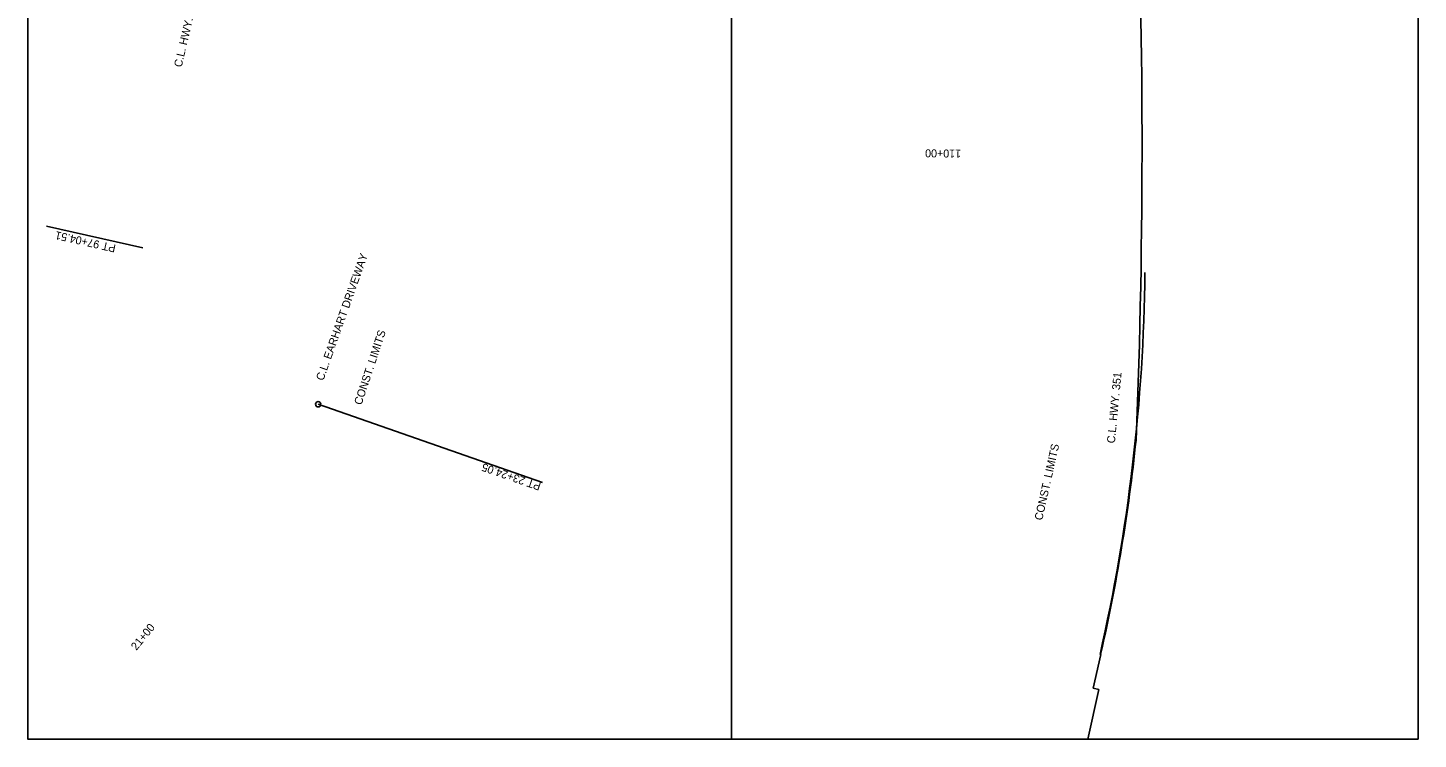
# Model space of a CAD drawing. Extents: x 1712161 to 1713203, y 549259 to 550855.
# Drawn here: x 1712161 to 1713203, y 549259 to 549792 of the extents above; entities that cross this region are included whole.
import ezdxf

# ---------------------------------------------------------------- set-up
doc = ezdxf.new("R2010")
doc.units = 0
for name, color, linetype in [('R_Contour Annot', 7, 'Continuous'), ('R_Contours', 7, 'Continuous'), ('R_Erosion', 7, 'Continuous'), ('R_Horz Alg Annot', 7, 'Continuous'), ('R_MOT', 7, 'Continuous')]:
    doc.layers.add(name, color=color, linetype=linetype)

msp = doc.modelspace()

# ---------------------------------------------------------------- linework, layer by layer
at = {"layer": 'R_Contour Annot'}
msp.add_lwpolyline([(1712361.5, 550854.5), (1712688.2, 550854.5), (1712688.2, 549259.2), (1712160.6, 549259.2), (1712160.6, 550443.2), (1712210, 550443.2), (1712210, 550620.8), (1712227.8, 550620.8), (1712227.8, 550639), (1712224.6, 550639), (1712224.6, 550716.7)], dxfattribs=at)
msp.add_lwpolyline([(1712361.5, 550854.5), (1712688.2, 550854.5), (1712688.2, 549259.2), (1712160.6, 549259.2), (1712160.6, 550443.2), (1712210, 550443.2), (1712210, 550620.8), (1712227.8, 550620.8), (1712227.8, 550639), (1712224.6, 550639), (1712224.6, 550716.7)], dxfattribs=at)
msp.add_lwpolyline([(1712361.5, 550854.5), (1712688.2, 550854.5), (1712688.2, 549259.2), (1712160.6, 549259.2), (1712160.6, 550443.2), (1712210, 550443.2), (1712210, 550620.8), (1712227.8, 550620.8), (1712227.8, 550639), (1712224.6, 550639), (1712224.6, 550716.7)], dxfattribs=at)
msp.add_lwpolyline([(1712361.5, 550854.5), (1712688.2, 550854.5), (1712688.2, 549259.2), (1712160.6, 549259.2), (1712160.6, 550443.2), (1712210, 550443.2), (1712210, 550620.8), (1712227.8, 550620.8), (1712227.8, 550639), (1712224.6, 550639), (1712224.6, 550716.7)], dxfattribs=at)
msp.add_lwpolyline([(1712361.5, 550854.5), (1712688.2, 550854.5), (1712688.2, 549259.2), (1712160.6, 549259.2), (1712160.6, 550443.2), (1712210, 550443.2), (1712210, 550620.8), (1712227.8, 550620.8), (1712227.8, 550639), (1712224.6, 550639), (1712224.6, 550716.7)], dxfattribs=at)
msp.add_lwpolyline([(1712361.5, 550854.5), (1712688.2, 550854.5), (1712688.2, 549259.2), (1712160.6, 549259.2), (1712160.6, 550443.2), (1712210, 550443.2), (1712210, 550620.8), (1712227.8, 550620.8), (1712227.8, 550639), (1712224.6, 550639), (1712224.6, 550716.7)], dxfattribs=at)
msp.add_lwpolyline([(1712361.5, 550854.5), (1712688.2, 550854.5), (1712688.2, 549259.2), (1712160.6, 549259.2), (1712160.6, 550443.2), (1712210, 550443.2), (1712210, 550620.8), (1712227.8, 550620.8), (1712227.8, 550639), (1712224.6, 550639), (1712224.6, 550716.7)], dxfattribs=at)
msp.add_lwpolyline([(1712361.5, 550854.5), (1712688.2, 550854.5), (1712688.2, 549259.2), (1712160.6, 549259.2), (1712160.6, 550443.2), (1712210, 550443.2), (1712210, 550620.8), (1712227.8, 550620.8), (1712227.8, 550639), (1712224.6, 550639), (1712224.6, 550716.7)], dxfattribs=at)
msp.add_lwpolyline([(1712688.2, 549259.2), (1712688.2, 550854.5), (1713202.9, 550854.5), (1713202.9, 549259.2)], close=True, dxfattribs=at)
msp.add_lwpolyline([(1712688.2, 549259.2), (1712688.2, 550854.5), (1713202.9, 550854.5), (1713202.9, 549259.2)], close=True, dxfattribs=at)
msp.add_lwpolyline([(1712688.2, 549259.2), (1712688.2, 550854.5), (1713202.9, 550854.5), (1713202.9, 549259.2)], close=True, dxfattribs=at)
msp.add_lwpolyline([(1712688.2, 549259.2), (1712688.2, 550854.5), (1713202.9, 550854.5), (1713202.9, 549259.2)], close=True, dxfattribs=at)
msp.add_lwpolyline([(1712688.2, 549259.2), (1712688.2, 550854.5), (1713202.9, 550854.5), (1713202.9, 549259.2)], close=True, dxfattribs=at)
msp.add_lwpolyline([(1712688.2, 549259.2), (1712688.2, 550854.5), (1713202.9, 550854.5), (1713202.9, 549259.2)], close=True, dxfattribs=at)
msp.add_lwpolyline([(1712688.2, 549259.2), (1712688.2, 550854.5), (1713202.9, 550854.5), (1713202.9, 549259.2)], close=True, dxfattribs=at)
msp.add_lwpolyline([(1712688.2, 549259.2), (1712688.2, 550854.5), (1713202.9, 550854.5), (1713202.9, 549259.2)], close=True, dxfattribs=at)
msp.add_lwpolyline([(1712688.2, 549259.2), (1712688.2, 550854.5), (1713202.9, 550854.5), (1713202.9, 549259.2)], close=True, dxfattribs=at)
at = {"layer": 'R_Contours'}
msp.add_arc((1711636.1, 549624.3), 1362.1, 347.2066, 359.3498, dxfattribs=at)
at = {"layer": 'R_Erosion'}
for points in [[(1712246.8, 549627.3), (1712174.5, 549643.7)], [(1712546.5, 549451.6), (1712378.3, 549510.2)]]:
    msp.add_lwpolyline(points, dxfattribs=at)
msp.add_circle((1712378.3, 549510.2), 2, dxfattribs=at)
at = {"layer": 'R_Horz Alg Annot'}
for p, q in [((1712688.2, 549914.6), (1712688.2, 549752.4)), ((1712688.2, 549752.4), (1712688.2, 549259.2))]:
    msp.add_line(p, q, dxfattribs=at)
at = {"layer": 'R_MOT'}
for p, q in [((1712991.5, 549483.4), (1712991.5, 549483.4)), ((1712959.2, 549297.3), (1712964.9, 549322.6)), ((1712955.2, 549259.2), (1712963.6, 549296.3)), ((1712963.6, 549296.3), (1712959.2, 549297.3))]:
    msp.add_line(p, q, dxfattribs=at)
msp.add_lwpolyline([(1713202.9, 549942.3), (1713202.9, 549259.2), (1712955.2, 549259.2)], dxfattribs=at)
for centre, radius, start, end in [((1707466.7, 549704.5), 5529.2, 357.7082, 2.4649), ((1711636.1, 549624.3), 1362.6, 347.2066, 354.0638)]:
    msp.add_arc(centre, radius, start, end, dxfattribs=at)

# ---------------------------------------------------------------- texts
at = {"layer": 'R_Erosion'}
for s, rotation, p in [('110+00', 179.3498, (1712860.3, 549701)), ('PT 97+04.51', 167.2066, (1712227, 549629.7)), ('PT 23+24.05', 160.7734, (1712545.8, 549451)), ('21+00', 50.6088, (1712242, 549325.3))]:
    msp.add_text(s, height=6, rotation=rotation, dxfattribs=at).set_placement(p)
at = {"layer": 'R_Horz Alg Annot'}
for s, rotation, p in [('C.L. HWY. 351', 76.7828, (1712275.9, 549762.4)), ('C.L. EARHART DRIVEWAY', 70.4957, (1712382.1, 549527.4)), ('CONST. LIMITS', 71.6235, (1712410.7, 549509.2)), ('C.L. HWY. 351', 84.5388, (1712975.5, 549480.7)), ('CONST. LIMITS', 77.27, (1712921, 549422.8))]:
    msp.add_text(s, height=6, rotation=rotation, dxfattribs=at).set_placement(p)

doc.saveas('drawing.dxf')
